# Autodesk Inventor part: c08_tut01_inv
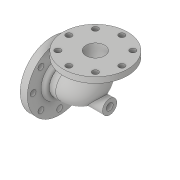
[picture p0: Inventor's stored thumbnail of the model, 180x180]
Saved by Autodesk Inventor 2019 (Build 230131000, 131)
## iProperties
Created: 2015-03
Part Number: c08_tut01_inv
Material: Generic
Document SubType Name: Modeling
Designer: Sandeep
Density: 1 g/cm^3
Appearance: Default
Author: Sandeep
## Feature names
1. Sweep1
2. Shell1
3. Extrusion1
4. Extrusion2
5. Extrusion3
6. Extrusion4
7. Fillet1
8. Extrusion5
9. Circular Pattern1
10. Extrusion6
11. Circular Pattern2
12. Extrusion7
13. Hole1
## Parameters: d1 = 35 mm, d2 = 35 mm, d4 = 97 mm, d5 = 0, d6 = 0, d7 = 16 mm, d8 = 225 mm, d10 = 0, d11 = 225 mm, d13 = 25 mm, d14 = 0, d15 = 86 mm, d16 = 22 mm, d17 = 0, d18 = 129 mm, d19 = 16 mm, d20 = 0, d21 = 16 mm, d22 = 185 mm, d23 = 20.5 mm, d24 = 0, d25 = 0, d27 = 360 deg, d29 = 185 mm, d30 = 20.5 mm, d31 = 16 mm, d32 = 0, d34 = 360 deg, d37 = 175 mm, d39 = 145 mm, d40 = 16 mm, d41 = 0, d45 = 6 mm, d46 = 24 mm, d47 = 28 mm, d48 = 90 deg, d49 = 8 mm, d50 = 118 deg
